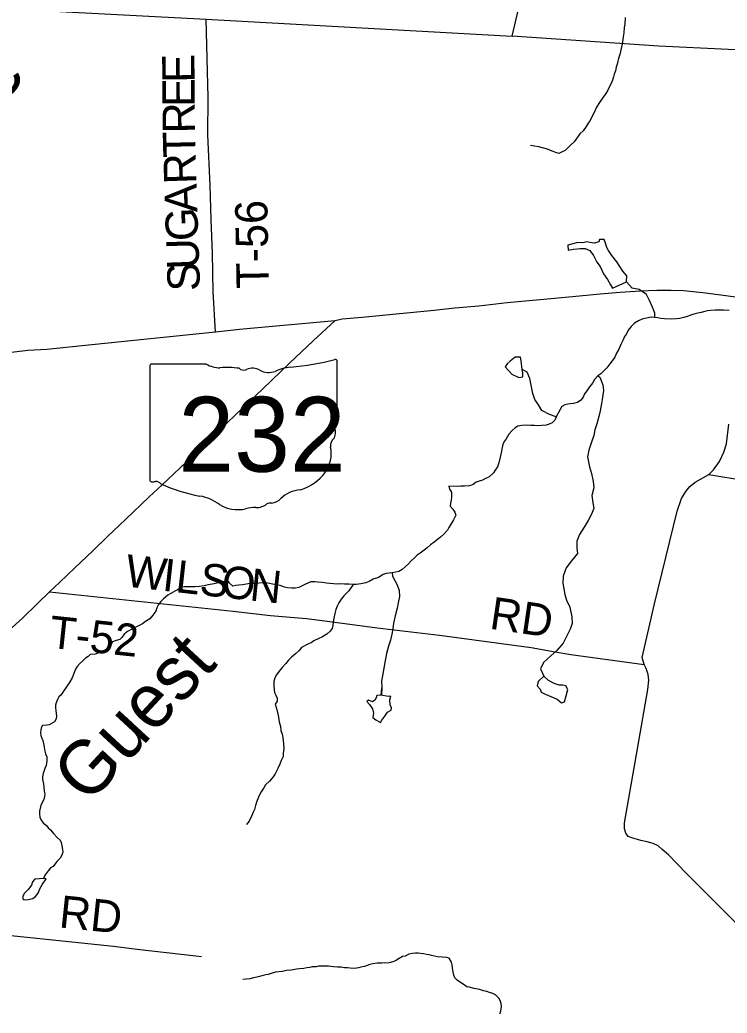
# Model space of a CAD drawing. Extents: x 1310247 to 1664935, y 235267 to 584339.
# Drawn here: x 1504409 to 1510976, y 347420 to 356649 of the extents above; entities that cross this region are included whole.
import ezdxf

# ---------------------------------------------------------------- set-up
doc = ezdxf.new("R2010")
doc.units = 0
for name, color, linetype in [('GM_X_County_Road', 7, 'Continuous'), ('GM_X_Minor_Lake', 7, 'Continuous'), ('GM_X_Minor_River', 7, 'Continuous'), ('GM_X_Minor_River_Text', 7, 'Continuous'), ('GM_X_State_Location', 7, 'Continuous'), ('GM_X_State_Route', 7, 'Continuous'), ('GM_X_State_Shield', 7, 'Continuous'), ('GM_X_Township_Road', 7, 'Continuous'), ('GM_X_Township_Road_Text', 7, 'Continuous')]:
    doc.layers.add(name, color=color, linetype=linetype)

msp = doc.modelspace()

# ---------------------------------------------------------------- linework, layer by layer
at = {"layer": 'GM_X_County_Road'}
for points in [[(1501913, 356901.5), (1501964.4, 356891.6), (1502237.6, 356862.4), (1506137.7, 356657.3), (1508978.5, 356498.9), (1509748.7, 359773.4), (1509841.4, 359902.5)], [(1511049.2, 356370.1), (1510343, 356406.5), (1508978.5, 356498.9)], [(1501410, 353094.5), (1501744.6, 353095.3), (1502037.9, 353104.1), (1502234.6, 353118.2), (1502436.6, 353127), (1502573.6, 353134), (1502693.5, 353139.4), (1502830, 353174.4), (1502947.7, 353211.2), (1503140.9, 353258.7), (1503356.9, 353318.4), (1503646.7, 353392.1), (1504101.7, 353513.3), (1504214.1, 353541.5), (1504272, 353552), (1504354.6, 353564.3), (1504481, 353580.1), (1504658.4, 353588.9), (1505076.4, 353634.5), (1506225.1, 353752.2), (1506448.2, 353775), (1507335.3, 353857.1)], [(1511132.1, 348186.4), (1510596.4, 348721.4), (1510430, 348890.5), (1510373.3, 348940.4), (1510336.3, 348973.4), (1510287.8, 348995.7), (1510233.9, 349011.1), (1510173.9, 349024.6), (1510091.7, 349050.2), (1510057.4, 349062.3), (1510035.7, 349091.3), (1510023.6, 349131.1), (1510023.6, 349187.7), (1510050.6, 349346.7), (1510143.6, 349875), (1510238.6, 350426.9), (1510247.3, 350513.1), (1510242.6, 350566.4), (1510225.1, 350623.6), (1510205.5, 350660.7), (1510188, 350726.1), (1510299.9, 351222), (1510512.8, 352085.9), (1510553.2, 352201.8), (1510591, 352267.8), (1510630.1, 352315), (1510678.6, 352354.1), (1510806.6, 352425.5), (1510848.4, 352468.6), (1510905, 352546.8), (1510944.1, 352633), (1510968.3, 352708.5), (1510992.6, 352891.8)]]:
    msp.add_lwpolyline(points, dxfattribs=at)
at = {"layer": 'GM_X_Minor_Lake'}
for points in [[(1510042.1, 354214.4), (1510043.1, 354270.6), (1510007.7, 354313.4), (1509953, 354400.6), (1509905.8, 354459.7), (1509874.5, 354506.4), (1509858.9, 354534.7), (1509845.5, 354575.1), (1509834.1, 354609.4), (1509792, 354610.1), (1509785.6, 354588.2), (1509743.2, 354574.8), (1509701.2, 354579.5), (1509673.2, 354586), (1509634.9, 354578.6), (1509588.8, 354579.4), (1509496.1, 354554.9), (1509499.4, 354508.6), (1509549.7, 354517.8), (1509581.8, 354521.3), (1509612, 354524.8), (1509658.1, 354526), (1509702, 354507.2), (1509735.3, 354458.5), (1509766.3, 354397.7), (1509797.8, 354359.1), (1509828.8, 354290.3)], [(1509828.8, 354290.3), (1509863.9, 354235.5), (1509893.2, 354186.8), (1509910.8, 354156.4), (1510042.1, 354214.4)], [(1509073.6, 353401.4), (1509062.9, 353479.9), (1509055.5, 353516.1), (1509007.3, 353514.9), (1508962.6, 353479.5), (1508932, 353451.9), (1508915.5, 353424.1), (1508976.6, 353358.8), (1509040.3, 353327.6)], [(1509040.3, 353327.6), (1509078.5, 353333), (1509079.2, 353371.2), (1509073.6, 353401.4)], [(1509117.4, 353376.5), (1509073.6, 353401.4)], [(1509274.8, 350551.4), (1509219.8, 350502.2), (1509211.1, 350460.2), (1509238.7, 350431.6), (1509248.2, 350403.4)], [(1509248.2, 350403.4), (1509274.1, 350388.9), (1509317.9, 350372.1), (1509397.6, 350336.6), (1509439.2, 350303.8), (1509465.4, 350311.4), (1509482.4, 350369.3), (1509495.4, 350427.3), (1509477.9, 350461.7), (1509449.9, 350468.2), (1509415.8, 350466.8), (1509369.9, 350481.6), (1509316.2, 350510.6), (1509274.8, 350551.4)], [(1507763.2, 350374), (1507768.4, 350444.1), (1507765.3, 350378)], [(1507723, 350372.6), (1507716.6, 350350.7), (1507704.2, 350328.8), (1507683.9, 350313.1), (1507646, 350327.8), (1507629.8, 350316), (1507653.4, 350287.5), (1507661.3, 350277.4), (1507682.8, 350246.9), (1507692.2, 350208.6), (1507685.5, 350166.6), (1507713.2, 350144), (1507756.9, 350121.2), (1507769.3, 350143.1), (1507796.1, 350180.8), (1507820.7, 350216.5), (1507857.2, 350235.9), (1507859.5, 350258), (1507846, 350286.3), (1507844.7, 350332.5), (1507853.3, 350366.5), (1507829.2, 350360.8), (1507763.2, 350374)], [(1507763.2, 350374), (1507723, 350372.6)], [(1504627.6, 348672), (1504547.4, 348665.3), (1504527, 348641.6), (1504516.4, 348609.7), (1504485.7, 348570.1), (1504463.2, 348548.4), (1504446.9, 348530.7), (1504436.4, 348502.8), (1504436, 348480.7), (1504444, 348476.6), (1504459.9, 348472.3), (1504490, 348475.8), (1504528.3, 348485.1), (1504554.7, 348504.7)], [(1504554.7, 348504.7), (1504577.2, 348534.4), (1504581.4, 348542.3), (1504591.8, 348568.2), (1504606.4, 348598.1), (1504618.8, 348617.9), (1504651.7, 348669.5), (1504627.6, 348672)]]:
    msp.add_lwpolyline(points, dxfattribs=at)
at = {"layer": 'GM_X_Minor_River'}
for points in [[(1510030.4, 356672), (1510025, 356605.9), (1510020.4, 356578), (1510015.3, 356527.9), (1510010.6, 356491.9), (1510003.5, 356443.9), (1509996.8, 356410), (1509990.2, 356382), (1509979.1, 356328.1), (1509966.3, 356290.2), (1509959.7, 356264.3), (1509955.2, 356238.3), (1509944.5, 356208.5), (1509937.9, 356176.5), (1509927.2, 356144.6), (1509920.6, 356118.7), (1509910, 356088.8), (1509897.4, 356059), (1509876.5, 356019.3), (1509863.9, 355989.5), (1509849.3, 355963.7), (1509824.6, 355930.2), (1509789.5, 355880.8), (1509762.6, 355837.2), (1509739.5, 355787.5), (1509720.7, 355749.8), (1509704, 355714), (1509685.4, 355688.4), (1509666.8, 355658.7), (1509639.9, 355619.1), (1509607.3, 355591.7), (1509555.7, 355516.6)], [(1509555.7, 355516.6), (1509516.9, 355481.3), (1509471.9, 355436.1), (1509443.6, 355422.6), (1509413.3, 355409.2), (1509385.5, 355415.8), (1509349.8, 355430.6), (1509308.1, 355447.5), (1509228.5, 355469.2), (1509186.6, 355476.1), (1509148.7, 355480.9)], [(1510305.8, 353884.4), (1510304.1, 353924.9), (1510283, 353979.5), (1510255.9, 354042.2), (1510226.8, 354096.9), (1510159.3, 354144.2), (1510093.3, 354155.3), (1510042.1, 354214.4)], [(1510995.6, 353948.2), (1510941.6, 353953.3), (1510905.6, 353952.1), (1510863.5, 353951), (1510825.5, 353947.7), (1510793.4, 353944.4), (1510767.2, 353938.9), (1510735, 353931.6), (1510702.9, 353924.2), (1510666.7, 353915), (1510638.4, 353905.5), (1510604.1, 353892.2), (1510573.9, 353882.8), (1510535.7, 353873.5), (1510505.6, 353870.2), (1510463.5, 353869), (1510393.5, 353870.5), (1510361.6, 353875.2), (1510331.7, 353881.8), (1510305.8, 353884.4), (1510271.8, 353887.1), (1510225.6, 353878), (1510191.4, 353870.7), (1510153, 353853.5), (1510116.5, 353830.1), (1510083.9, 353800.8), (1510057.1, 353765.2), (1510040.4, 353733.5), (1510021.8, 353705.8), (1510009.2, 353676), (1509988.3, 353634.3), (1509969.4, 353590.6), (1509948.5, 353552.9), (1509931.7, 353515.1), (1509907, 353481.5), (1509886.4, 353453.9), (1509859.6, 353416.4), (1509831, 353388.9), (1509804.4, 353361.4), (1509776, 353341.9), (1509745.3, 353308.5), (1509724.5, 353274.8), (1509697.8, 353239.2), (1509673, 353203.7), (1509650.4, 353176), (1509637.7, 353144.2), (1509617.1, 353114.6), (1509586.6, 353093.1), (1509550.4, 353083.9), (1509522.3, 353080.5), (1509496.3, 353079), (1509468.1, 353073.6), (1509439.8, 353058.1), (1509425.1, 353028.3), (1509389.7, 352960.9), (1509375.1, 352931.1), (1509350.5, 352905.6), (1509324.2, 352894.1), (1509294, 352882.7), (1509255.9, 352881.5), (1509219.8, 352878.2), (1509185.8, 352878.9), (1509149.9, 352881.7), (1509109.9, 352882.5), (1509069.8, 352881.3), (1509033.6, 352874.1), (1509007.3, 352858.6), (1508978.7, 352833.1), (1508948, 352799.6), (1508925.1, 352756), (1508906.5, 352730.3), (1508891.9, 352702.6), (1508887.3, 352674.6), (1508878.3, 352626.6), (1508869.4, 352584.7), (1508856.3, 352532.8), (1508843.5, 352495), (1508822.9, 352465.4), (1508806.3, 352439.6)], [(1509389.7, 352960.9), (1509327.5, 352983.5), (1509255.9, 353020.9), (1509222.6, 353071.6), (1509191.4, 353122.3), (1509172.2, 353178.9), (1509155.5, 353255.5), (1509144.5, 353317.9), (1509117.4, 353376.5)], [(1509776, 353341.9), (1509794.7, 353329.1), (1509821.5, 353258.4), (1509828.7, 353206), (1509819.6, 353139.9), (1509808.6, 353083.9), (1509797.4, 353015.8), (1509784.5, 352963.8), (1509765.3, 352895.9), (1509748.4, 352840), (1509737.5, 352788), (1509720.5, 352734), (1509691, 352650.2), (1509678, 352590.2), (1509696.5, 352497.5), (1509717.5, 352435), (1509732.3, 352360.4), (1509737.4, 352302.1), (1509718.1, 352230.2), (1509729, 352161.7), (1509738.2, 352109.4), (1509713.1, 352051.6), (1509684.1, 351997.9), (1509647, 351934.2), (1509603.7, 351866.7), (1509578.6, 351804.9), (1509581.6, 351744.6), (1509586.8, 351692.3), (1509529.4, 351623.1), (1509480.2, 351557.6), (1509452.8, 351479.8), (1509449.7, 351415.6), (1509458.9, 351363.3), (1509470, 351310.9), (1509485.2, 351258.5), (1509514.2, 351191.7), (1509532.8, 351103.1), (1509535.7, 351040.8), (1509516.8, 350987), (1509487.7, 350925.2), (1509452.4, 350857.6), (1509393.1, 350790.3), (1509338.1, 350739), (1509270.9, 350677.9), (1509241.8, 350620.2), (1509274.8, 350551.4)], [(1508806.3, 352439.6), (1508761.5, 352400.5), (1508731.2, 352387.1), (1508702.9, 352373.6), (1508672.6, 352362.2), (1508646.4, 352354.7), (1508617.9, 352331.3), (1508583.6, 352320), (1508537.5, 352316.9), (1508503.5, 352315.6), (1508473.4, 352314.2), (1508391.4, 352316), (1508396.8, 352287.8), (1508416.3, 352261.3), (1508417.4, 352217.1), (1508412.7, 352187.2), (1508406.1, 352157.2), (1508403.5, 352131.2), (1508428.9, 352102.6), (1508448.4, 352076.1), (1508457.8, 352047.9), (1508434.9, 352004.2), (1508416.2, 351972.5), (1508391.3, 351932.9), (1508378.8, 351907.1), (1508346, 351871.7), (1508313.4, 351844.3), (1508284.9, 351820.9), (1508254.4, 351797.5), (1508221.8, 351770.1), (1508191.2, 351742.6), (1508162.7, 351721.2), (1508126.1, 351693.8), (1508097.7, 351674.4), (1508069.1, 351648.9), (1508042.5, 351621.4), (1508018, 351595.8), (1507985.3, 351566.5), (1507956.8, 351541), (1507928.4, 351523.5), (1507898.2, 351516.1), (1507866.1, 351510.8), (1507838, 351509.4), (1507810, 351506), (1507781.7, 351494.5), (1507737.1, 351467.4), (1507688.7, 351452.3), (1507652.3, 351431), (1507622, 351419.6), (1507575.7, 351408.6), (1507531.6, 351403.5), (1507503.6, 351402.1), (1507463.6, 351404.9), (1507423.6, 351405.7), (1507385.6, 351408.5), (1507353.6, 351407.2), (1507285.6, 351412.6), (1507255.7, 351415.3), (1507215.8, 351422.1), (1507175.8, 351424.9), (1507145.9, 351427.6), (1507109.8, 351426.3), (1507061.4, 351407.3), (1507029, 351389.9), (1506998.7, 351376.5), (1506964.5, 351369.2), (1506932.5, 351367.9), (1506894.5, 351372.7), (1506866.7, 351379.3), (1506824.9, 351394.2), (1506787.1, 351401), (1506755.1, 351405.7), (1506725.3, 351412.3), (1506691.3, 351417), (1506659.3, 351417.7), (1506631.2, 351414.3), (1506595.2, 351413), (1506557.1, 351411.8), (1506529, 351408.4), (1506476.9, 351401.4), (1506442.8, 351398.1), (1506414.6, 351392.7), (1506384.5, 351387.3)], [(1507866.1, 351510.8), (1507867.9, 351480.2), (1507910.8, 351401.2), (1507931.9, 351346.6), (1507933, 351290.4), (1507922, 351232.4), (1507913.1, 351182.4), (1507893.9, 351112.4), (1507878.7, 351042.4), (1507871.8, 350992.4), (1507862.9, 350940.3), (1507850, 350884.3), (1507831, 350830.5), (1507813.8, 350760.5), (1507798.4, 350678.5), (1507787.4, 350624.5), (1507778.5, 350572.4), (1507765.4, 350504.4), (1507768.4, 350444.1)], [(1506384.5, 351387.3), (1506354, 351416.1), (1506345, 351432), (1506314.8, 351428.5), (1506294.7, 351426.9), (1506272.5, 351421.2), (1506238.2, 351415.8), (1506212, 351410.2), (1506175.6, 351402.8), (1506143.4, 351395.3), (1506121.2, 351391.7), (1506074.8, 351384.5), (1506032.6, 351381.2), (1505972.3, 351382.2), (1505934.1, 351380.8), (1505909.9, 351377.2), (1505873.3, 351353.8), (1505848.9, 351342.1), (1505781.9, 351305.1), (1505741.1, 351269.6), (1505716.6, 351246), (1505696, 351218.2), (1505681.3, 351186.3), (1505670.7, 351156.3), (1505643.9, 351118.6), (1505615.1, 351083), (1505576.5, 351059.5), (1505548, 351037.9), (1505521.6, 351024.3), (1505491.2, 351008.8), (1505454.7, 350991.3), (1505408, 350966), (1505375.4, 350940.5), (1505356.7, 350910.6), (1505336.3, 350890.9), (1505304, 350883.4), (1505267.6, 350870), (1505255.1, 350848.1), (1505226.3, 350812.4), (1505209.9, 350790.6), (1505175.4, 350775.1), (1505147.2, 350769.6), (1505106.7, 350756.2), (1505062.4, 350751), (1505042, 350735.2), (1505017.6, 350719.6), (1504997.1, 350695.8), (1504966.5, 350670.3), (1504941.8, 350640.5), (1504925.3, 350614.7), (1504910.5, 350576.8), (1504893.7, 350536.9), (1504872.9, 350497.1), (1504852.3, 350469.3), (1504835.7, 350443.5), (1504819.3, 350421.7), (1504790.3, 350376), (1504769.9, 350358.3), (1504757.4, 350334.4), (1504746.8, 350302.5), (1504738.4, 350282.5), (1504738, 350260.4), (1504743.4, 350228.2), (1504748.6, 350183.9), (1504746.1, 350153.8), (1504729.5, 350128), (1504707.2, 350114.3), (1504680.8, 350098.7), (1504658.6, 350097.1), (1504618.3, 350091.8), (1504605.9, 350071.9), (1504603.5, 350049.8), (1504601.1, 350025.8), (1504604.6, 349999.6), (1504612.2, 349975.4), (1504621.8, 349953.1), (1504629.4, 349926.9), (1504634.8, 349892.6), (1504640.2, 349854.4), (1504647.7, 349828.1), (1504659.3, 349801.8), (1504658.6, 349765.7), (1504653.8, 349719.6), (1504641.3, 349693.7), (1504626.3, 349645.8), (1504619.7, 349615.7), (1504619.3, 349589.6), (1504626.6, 349551.4), (1504632.1, 349519.1), (1504635.4, 349482.9), (1504639, 349456.8), (1504636.5, 349432.7), (1504632, 349404.7), (1504619.5, 349382.8), (1504602.8, 349348.9), (1504589.8, 349297), (1504589.4, 349270.9), (1504594.8, 349240.6), (1504606.4, 349214.3), (1504626.1, 349187.9), (1504657.7, 349161.2)], [(1507503.6, 351402.1), (1507462.3, 351342.8), (1507415.3, 351297.6), (1507392.7, 351268), (1507369.9, 351232.4), (1507353.3, 351202.7), (1507342.6, 351170.8), (1507331.8, 351135), (1507324.9, 351091), (1507318.1, 351055.1), (1507315.4, 351023), (1507306.8, 350995.2), (1507290.3, 350969.4), (1507257.6, 350940), (1507211.1, 350915), (1507184.8, 350901.5), (1507138.3, 350880.4), (1507111.9, 350860.9), (1507083.6, 350847.5), (1507024.9, 350816.6), (1507002.3, 350791), (1506967.6, 350759.6), (1506930.9, 350726.3), (1506902.4, 350700.9), (1506877.7, 350669.3), (1506842.9, 350631.9), (1506816.1, 350598.4), (1506791.4, 350564.8), (1506774.8, 350537.1), (1506766, 350501.2), (1506765.2, 350461.1), (1506770.5, 350427), (1506773.9, 350400.8), (1506785.4, 350374.5), (1506798.8, 350346.2), (1506796.2, 350320.2), (1506779.6, 350290.5), (1506787, 350260.2), (1506798.3, 350227.9), (1506809.1, 350169.6), (1506816.2, 350127.3), (1506827.2, 350083), (1506832.4, 350044.8), (1506843.8, 350012.5), (1506851.1, 349980.2), (1506854.5, 349952.1), (1506855.9, 349922), (1506858.9, 349875.8), (1506854, 349835.9), (1506853.4, 349805.8), (1506834.6, 349766.1), (1506821.9, 349734.3), (1506803, 349692.6), (1506777.9, 349643), (1506759.4, 349617.3), (1506726.5, 349576), (1506689.7, 349542.6), (1506673.1, 349512.9), (1506650.3, 349477.3), (1506629.6, 349443.7), (1506616.9, 349411.9), (1506606.3, 349380), (1506597.6, 349348.1), (1506586.8, 349312.3), (1506574.3, 349286.5), (1506563.6, 349256.7), (1506538.5, 349205.1), (1506513.8, 349173.5)], [(1504657.7, 349161.2), (1504671.4, 349140.9), (1504693.2, 349122.5), (1504720.7, 349089.9), (1504756.3, 349053.1), (1504783.9, 349026.5), (1504791.6, 349004.3), (1504797.1, 348976.1), (1504804.4, 348939.8), (1504806, 348915.7), (1504799.5, 348887.7), (1504782.9, 348859.9), (1504752.2, 348828.3), (1504717.2, 348782.7), (1504692.8, 348769.1), (1504670.2, 348743.4), (1504643.4, 348703.7), (1504627.6, 348672)], [(1507962.8, 347944.9), (1507930.4, 347927.6), (1507904.1, 347912.1), (1507879.8, 347900.6), (1507849.5, 347889.2), (1507825.4, 347885.7), (1507791.4, 347886.4), (1507769.4, 347884.8), (1507747.4, 347885.3), (1507725.3, 347883.8), (1507687.2, 347878.5), (1507657, 347871.2), (1507632.9, 347863.6), (1507608.6, 347854.1), (1507574.5, 347846.8), (1507552.3, 347841.3), (1507514.2, 347836.1), (1507476.2, 347836.9), (1507450.3, 347841.4), (1507422.3, 347842), (1507392.3, 347846.6), (1507356.3, 347847.4), (1507320.4, 347850.1), (1507296.4, 347854.6), (1507274.5, 347857.1), (1507230.5, 347858), (1507180.4, 347855.1), (1507158.3, 347851.5), (1507122.2, 347850.3), (1507100.1, 347844.7), (1507072, 347841.3), (1507045.9, 347835.8), (1507003.7, 347830.7), (1506975.7, 347829.3), (1506947.6, 347823.8), (1506925.5, 347820.3), (1506887.4, 347817.1), (1506845.2, 347808), (1506813, 347802.6), (1506780.9, 347799.3), (1506750.8, 347791.9), (1506714.5, 347780.6), (1506692.4, 347777.1), (1506656.1, 347765.8), (1506634, 347760.3), (1506607.9, 347754.8), (1506577.7, 347747.4), (1506543.5, 347740.1), (1506509.4, 347734.8), (1506479.3, 347731.5)], [(1508866.2, 347415.2), (1508874.7, 347439), (1508879.6, 347481), (1508878.2, 347511.1), (1508868.8, 347537.3), (1508855.2, 347559.6), (1508825.9, 347590.3), (1508800.1, 347602.9), (1508770.3, 347611.5), (1508744.4, 347620.1), (1508712.6, 347626.8), (1508674.8, 347639.6), (1508627, 347648.6), (1508581.2, 347661.5), (1508559.2, 347664), (1508523.7, 347688.8), (1508500, 347703.3), (1508468.5, 347728), (1508447, 347748.5), (1508437.5, 347772.7), (1508432.1, 347802.9), (1508424.9, 347841.1), (1508421.5, 347869.2), (1508416, 347893.4), (1508394.8, 347931.9), (1508372.9, 347936.4), (1508330.9, 347939.3), (1508285, 347944.2), (1508259.1, 347950.8), (1508231.2, 347955.4), (1508209.3, 347961.8), (1508183.3, 347964.4), (1508155.5, 347971), (1508127.5, 347973.5), (1508105.5, 347976), (1508081.5, 347976.5), (1508053.5, 347975.1), (1508021.3, 347967.8), (1507986.9, 347950.4), (1507962.8, 347944.9)]]:
    msp.add_lwpolyline(points, dxfattribs=at)
at = {"layer": 'GM_X_State_Route'}
for points in [[(1507335.3, 353857.1), (1507402.2, 353870), (1507586.4, 353887.2), (1507902.5, 353918.3), (1508223.4, 353949.8), (1508448.2, 353972.8), (1508670.1, 353993.4), (1508931.8, 354022.5), (1509240.2, 354051.7), (1509604.7, 354085.6), (1509797.1, 354102.4), (1509981.6, 354118.6), (1510170, 354131.1), (1510322.1, 354137.3), (1510456.5, 354139.2), (1510569.4, 354133.5), (1510748.7, 354117.2), (1510962.5, 354089.5), (1511208.5, 354055.5)], [(1504228.4, 350896.1), (1504304.9, 350974.5), (1504432.6, 351090.2), (1504573.2, 351227.9), (1504682.7, 351335.6), (1504776.5, 351422.1), (1504917.6, 351558), (1505086.9, 351716.8), (1505222.7, 351849.7), (1505389.6, 352007.5), (1505610.1, 352217.5), (1505728.2, 352329.4), (1505838.7, 352432.7), (1505955.4, 352544.2), (1506096.5, 352681.4), (1506256.2, 352831.6), (1506409.3, 352980.4), (1506664.7, 353221.4), (1506911.5, 353458.6), (1507132.9, 353668.6), (1507335.3, 353857.1)]]:
    msp.add_lwpolyline(points, dxfattribs=at)
at = {"layer": 'GM_X_State_Shield'}
for p, q in [((1505614.6, 353432.7), (1505614.6, 352376.1)), ((1506141.4, 353450.9), (1505631.8, 353450.9)), ((1507354.8, 352924.4), (1507354.8, 353477.1)), ((1507354.7, 352924.5), (1507354.8, 352924.4))]:
    msp.add_line(p, q, dxfattribs=at)
for centre, major_axis, start_param, end_param in [((1506735, 354891.5), (1845.5, 0), 4.814394, 5.042369), ((1507335.5, 353479.4), (19.4, 0), 6.141152, 7.989035), ((1505634.6, 353435), (20.2, 0), 1.712693, 3.28349), ((1506262.8, 353573.6), (195.5, 0), 4.042523, 4.731795), ((1506327.6, 352857.7), (702, 0), 1.404758, 1.657858), ((1506487, 353440.5), (56.4, 0), 3.836095, 5.185415), ((1506569.8, 353318.3), (117.3, 0), 0.950623, 2.079405), ((1506721.2, 353485.8), (141.1, 0), 4.081561, 5.145723), ((1506970.3, 353128.2), (371.3, 0), 1.699011, 2.107814), ((1507350.4, 352883.8), (30, 0), 1.883978, 3.671073), ((1507159.6, 352813.9), (180, 0), 5.934695, 6.695948), ((1507334.2, 352922.2), (20.7, 0), 5.05454, 6.418171), ((1507424.2, 352693), (130.9, 0), 2.387724, 3.262537), ((1506838.3, 352622.7), (461.6, 0), 5.101752, 6.440018), ((1505634.8, 352373.8), (20.3, 0), 3.00124, 4.508301), ((1505637.8, 352481.9), (155.2, 0), 4.665946, 4.897461), ((1505669.6, 352315.1), (56, 0), 0.519207, 1.627899), ((1506376.2, 353264.5), (1332.7, 0), 4.195997, 4.488961), ((1505978.9, 351901.4), (417, 0), 0.823519, 1.323587), ((1506712.7, 352273.7), (149.1, 0), 4.937069, 5.64225), ((1507033, 352079.4), (252.8, 0), 1.647645, 2.488434), ((1506429.8, 352309.9), (264.6, 0), 4.026481, 4.996735), ((1506582.7, 351944.6), (217.4, 0), 1.495662, 1.94098), ((1506602.1, 352230.8), (141, 0), 4.691044, 5.507374), ((1506729.6, 352128.4), (39.7, 0), 1.147584, 2.315152)]:
    msp.add_ellipse(centre, major_axis=major_axis, ratio=0.8, start_param=start_param, end_param=end_param, dxfattribs=at)
at = {"layer": 'GM_X_Township_Road'}
for points in [[(1506225.1, 353752.2), (1506202.3, 354121), (1506197, 354481.1), (1506184.7, 354793.7), (1506174.2, 355109.9), (1506153.1, 355580.6), (1506158.3, 355926.6), (1506137.7, 356657.3)], [(1510806.6, 352425.5), (1511816.4, 352257.9), (1511960.4, 352238.4), (1512000.5, 352238), (1512050.7, 352251.5), (1512163.4, 352310.5), (1512290.4, 352387.5), (1512326.7, 352405.1), (1512362.7, 352406.8), (1512432.7, 352396), (1512838.7, 352331.8), (1513718.7, 352192.6), (1513818.6, 352165.6), (1513884.4, 352142.9), (1513946.2, 352104.2), (1514019.6, 352041.3), (1514093.1, 351982.4), (1514144.7, 351933.7), (1514180.3, 351885.2), (1514232, 351848.6), (1514297.7, 351807.9), (1514355.6, 351789.3), (1514439.7, 351778.4), (1514667.9, 351766.1)], [(1504682.7, 351335.6), (1506388.9, 351153.7), (1506735.1, 351116.1), (1507069.3, 351086.6), (1507239.4, 351064.8), (1507727.5, 351001.8), (1508305.7, 350931.8), (1509155.9, 350816.9), (1509377.8, 350778.7), (1509525.8, 350753.1), (1510205.5, 350660.7)], [(1501594.3, 348424.4), (1501648.5, 348419), (1505277.3, 348041.4), (1505498.7, 348013.6), (1506042, 347952), (1506095.3, 347945.9)]]:
    msp.add_lwpolyline(points, dxfattribs=at)

# ---------------------------------------------------------------- texts
at = {"layer": 'GM_X_Minor_River_Text'}
for s, height, rotation, p in [('Sugartree', 500.06, 50.0056, (1502593, 353886.2)), ('Guest', 499.91, 47.22856, (1505041.2, 349349.2))]:
    msp.add_text(s, height=height, rotation=rotation, dxfattribs=at).set_placement(p)
at = {"layer": 'GM_X_State_Location'}
msp.add_text('232', height=1, rotation=0.00001, dxfattribs=at).set_placement((1506112.2, 352761.4))
for s in ['s', 'r']:
    msp.add_text(s, height=1, dxfattribs=at).set_placement((1506465.2, 352834.2))
at = {"layer": 'GM_X_State_Shield'}
msp.add_text('232', height=696.1, dxfattribs=at).set_placement((1505880.4, 352450.6))
at = {"layer": 'GM_X_Township_Road_Text'}
for s, rotation, p in [('E', 90.32143, (1506030.7, 356065.9)), ('E', 90.33429, (1506032.1, 355841.5)), ('R', 90.68695, (1506035, 355595.6)), ('T', 91.41866, (1506040.5, 355372.3)), ('R', 91.89329, (1506048.7, 355126.7)), ('A', 91.91644, (1506057.5, 354862.9)), ('T-56', 91.06046, (1506720.8, 354153.2)), ('G', 91.92008, (1506066.3, 354599)), ('U', 91.92008, (1506075.2, 354335.1)), ('S', 91.91992, (1506082, 354132.9)), ('W', 353.59977, (1505377.3, 351385.6)), ('I', 353.59731, (1505722.8, 351346.9)), ('L', 353.59972, (1505845.2, 351333.1)), ('S', 353.59927, (1506068.2, 351308.1)), ('O', 353.60507, (1506269.4, 351285.6)), ('N', 354.09434, (1506534.5, 351255.9)), ('RD', 351.66169, (1508760.9, 350993.4)), ('T-52', 353.97237, (1504671.5, 350816.5)), ('RD', 354.09415, (1504764.7, 348217.7))]:
    msp.add_text(s, height=300, rotation=rotation, dxfattribs=at).set_placement(p)

doc.saveas('drawing.dxf')
